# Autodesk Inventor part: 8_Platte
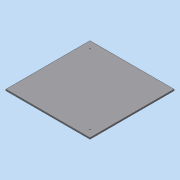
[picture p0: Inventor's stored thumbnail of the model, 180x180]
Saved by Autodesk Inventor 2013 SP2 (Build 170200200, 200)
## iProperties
Created: 2014-01
Part Number: 8_Platte
Material: Allgemein
Document SubType Name: Modeling
Designer: J. Palme
Density: 1 g/cm^3
Author: J. Palme
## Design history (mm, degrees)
sketch "Skizze1"
  geometry: L1 (0, 0)-(120, 0); L2 (120, 0)-(120, 120); L3 (120, 120)-(0, 120); L4 (0, 120)-(0, 0); C1 r 0.515 at (10, 110); C2 r 0.577 at (110, 10)
  constraints: 8 end point, 2 centre point, 2 parallel, 1 horizontal, 1 perpendicular
  dimensions: "d2" = 10 distance from line of C2.centre L1; "d3" = 10 distance from line of C1.centre L4; "d4" = 10 distance from line of L2 C2.centre; "d7" = 100 horizontal distance of C2.centre C1.centre; "d10" = 10 distance from line of C1.centre L3; "d11" = 100 horizontal distance of C2.centre C1.centre
extrude "Extrusion1" new body sketch "Skizze1" distance "d8" = 2; taper "d9" = 0 deg
node "Volumenkörper1"
